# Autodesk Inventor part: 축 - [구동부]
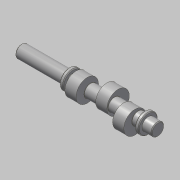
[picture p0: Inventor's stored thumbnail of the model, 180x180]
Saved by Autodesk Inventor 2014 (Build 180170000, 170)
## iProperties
Company: 한국ATC센터
Created: 2014-08
Part Number: 축 - [구동부]
Document SubType Name: Modeling
Designer: mdu
Density: 7.86 g/cm^3
Material: 강철, 연강
Mass: 516.584 g
Surface Area: 162.516 cm^2
Volume: 65.7231 cm^3
Appearance: 강철
Author: mdu
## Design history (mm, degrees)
sketch "스케치1"
  geometry: L1 (-91.5, 0)-(91.5, 0); L2 (-91.5, 0)-(-91.5, 8.5); L3 (-91.5, 8.5)-(-27.5, 8.5); L4 (-27.5, 8.5)-(-27.5, 13); L5 (-27.5, 13)-(-22.5, 13); L6 (-22.5, 13)-(-22.5, 8.5); L7 (-22.5, 8.5)-(73.5, 8.5); L8 (73.5, 8.5)-(73.5, 13); L9 (73.5, 13)-(78.5, 13); L10 (78.5, 13)-(78.5, 8.5); L11 (78.5, 8.5)-(91.5, 8.5); L12 (91.5, 8.5)-(91.5, 0); 2 further points
  constraints: 24 end point, 5 parallel, 1 coincident, 1 horizontal, 1 midpoint, 1 perpendicular
  dimensions: "d0" = 183 distance of L1.start L1.end (derived); "d2" = 17 diameter of L3 L1; "d3" = 26 diameter of L5 L1; "d4" = 17 diameter of L7 L1; "d5" = 26 diameter of L9 L1; "d6" = 17 diameter of L11 L1; "d7" = 5 distance of L8.end L9.end; "d8" = 5 distance of L4.end L5.end; "d10" = 64 distance of L2.end L3.end; "d11" = 13 distance of L10.end L11.end; "d35" = 96 distance between parallel lines of L8 L6
revolve "회전1" sketch "스케치1" stored, may be unused: angle "d12" = 90 deg
node "작업 평면7"
sketch "스케치6"
  geometry: C1 r 15 at (0, 5); 1 further point
  constraints: 1 centre point, 1 vertical alignment
  dimensions: "d37" = 30 diameter of C1; "d38" = 5 distance of C1.centre point (0, 0)
extrude "돌출4" join sketch "스케치6" stored distance "d33" = 15; taper "d34" = 0 deg
node "작업 평면8"
sketch "스케치7"
  geometry: L1 (0, 0)-(-6.5, -11.258); L2 (0, 0)-(13, 0); C1 r 15 at (-2.5, -4.33); A1 r 13 centre (0, 0) between (-6.5, -11.258) and (13, 0) reference; 1 further point
  constraints: 4 end point, 2 point on circle, 1 centre point, 1 horizontal, 1 point on line
  dimensions: "d40" = 120 deg angle of L1 L2; "d41" = 30 diameter of C1; "d42" = 5 distance of point (0, 0) C1.centre
extrude "돌출5" join sketch "스케치7" stored distance "d43" = 15; taper "d44" = 0 deg
node "작업 평면9"
sketch "스케치8"
  geometry: L1 (0, 0)-(4.25, -7.361); L2 (0, 0)-(-8.5, 0); C1 r 15 at (2.5, -4.33); A1 r 8.5 centre (0, 0) between (4.25, -7.361) and (-8.5, 0) reference; 1 further point
  constraints: 4 end point, 2 point on circle, 1 centre point, 1 horizontal, 1 point on line
  dimensions: "d46" = 120 deg angle of L1 L2; "d47" = 30 diameter of C1; "d48" = 5 distance of point (0, 0) C1.centre
extrude "돌출6" join sketch "스케치8" stored distance "d49" = 15; taper "d50" = 0 deg
node "작업 평면3"
sketch "스케치5"
  geometry: L1 (32, 8.5)-(32, -8.5) reference; L2 (27.5, -2.5)-(14.5, -2.5); L3 (14.5, 2.5)-(27.5, 2.5); A1 r 2.5 centre (14.5, 0) between (14.5, 2.5) and (14.5, -2.5); A2 r 2.5 centre (27.5, 0) between (27.5, -2.5) and (27.5, 2.5); 4 further points
  constraints: 4 end point, 4 point on circle, 4 tangent, 2 centre point, 2 point on line, 1 horizontal alignment, 1 midpoint, 1 parallel, 1 perpendicular
  dimensions: "d23" = 5 distance between parallel lines of L3 L2; "d36" = 20 dimension on A1 L1; "d52" = 2 distance edge to line of A2 L1
extrude "돌출3" cut sketch "스케치5" distance "d25" = 3; taper "d26" = 0 deg
chamfer "모따기1" distance "d27" = 1; stored, may be unused: second distance "d28" = 2, angle "d29" = 45 deg
fillet "모깎기1" dims "d51" = 0.3
chamfer "모따기2" distance "d53" = 1; stored, may be unused: second distance "d54" = 2, angle "d55" = 45 deg
node "작업 평면10"
node "솔리드1"
other parameters: "d39" = -32, "d45" = 32
